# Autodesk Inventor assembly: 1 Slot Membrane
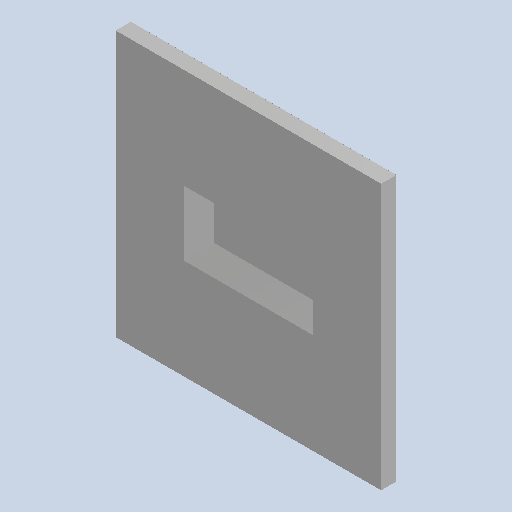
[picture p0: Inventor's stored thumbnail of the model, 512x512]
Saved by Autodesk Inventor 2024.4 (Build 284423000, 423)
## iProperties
Created: 2025-08
Part Number: 1 Slot Membrane
Document SubType Name: Assembly
Designer: AdminForWorker
Title: 1 Slot Membrane v3
Author: AdminForWorker
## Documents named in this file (3)
- c:\worker\convert-fusion-r04-cosv3\tmp\job-1\30\temp\files\a75cde7b-f010-4767-a07e-3224bb590113\d1f116fe-5af9-46a7-aa80-544e33a14a46.iam
- c:\worker\convert-fusion-r04-cosv3\tmp\job-1\30\temp\files\a75cde7b-f010-4767-a07e-3224bb590113\1-Slot Membrane.ipt
- c:\worker\convert-fusion-r04-cosv3\tmp\job-1\30\temp\files\a75cde7b-f010-4767-a07e-3224bb590113\Pore Layer.ipt
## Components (2 placed, 2 different names)
1. 1-Slot Membrane:1
2. Pore Layer:1
